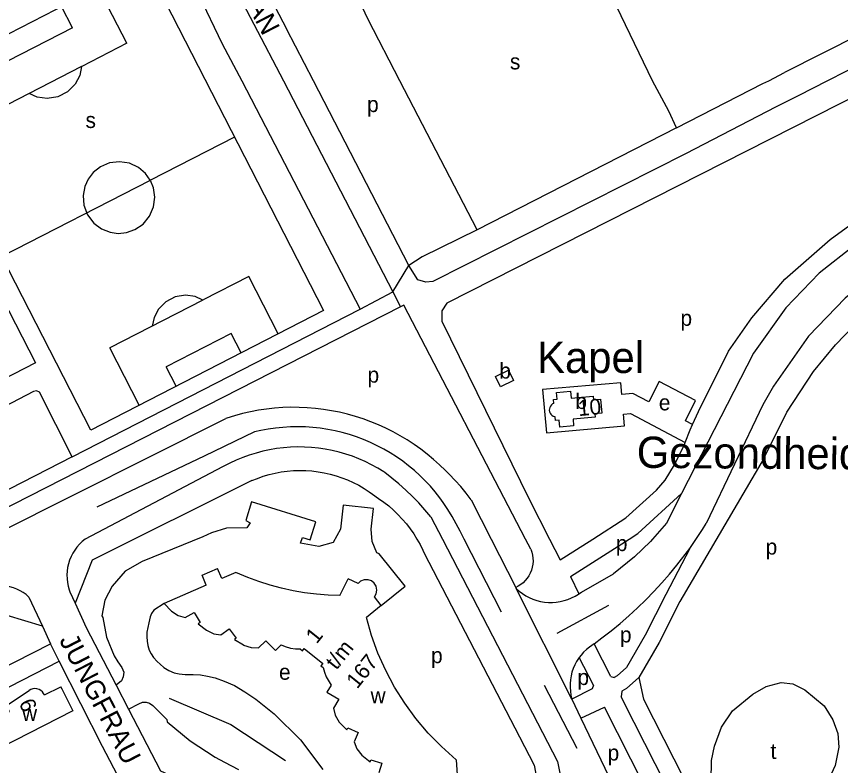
# Model space of a CAD drawing. Extents: x 158848 to 160613, y 385889 to 387762.
# Drawn here: x 159449.2 to 159660, y 386924.8 to 387116.4 of the extents above; entities that cross this region are included whole.
import ezdxf

# ---------------------------------------------------------------- set-up
doc = ezdxf.new("R2010")
doc.units = 0
for name, color, linetype in [('BLT_Basislijn', 7, 'Continuous'), ('BLT_Bebouwing', 7, 'Continuous'), ('BLT_Bebouwing_beschrifting', 7, 'Continuous'), ('BLT_Centroide', 7, 'Continuous'), ('BLT_Huisnummer', 7, 'Continuous'), ('BLT_Huisnummer_reeks', 7, 'Continuous'), ('BLT_Straatnaam', 7, 'Continuous'), ('BLT_Vlakafsluiter', 7, 'Continuous')]:
    doc.layers.add(name, color=color, linetype=linetype)

msp = doc.modelspace()

# ---------------------------------------------------------------- linework, layer by layer
at = {"layer": 'BLT_Basislijn'}
for p, q in [((159712.26, 387135.93), (159645.73, 387102.09)), ((159422.56, 387099.42), (159482.14, 387130.03)), ((159477.37, 387109.59), (159470.08, 387123.78)), ((159463.48, 387113.51), (159460.68, 387118.95)), ((159463.48, 387113.51), (159447.03, 387105.06)), ((159477.37, 387109.59), (159465.86, 387103.67)), ((159465.8, 387103.64), (159441.7, 387091.26)), ((159618.04, 387087.93), (159640.13, 387099.3)), ((159649.19, 387096.1), (159643.38, 387093.22)), ((159618.04, 387087.93), (159567.07, 387061.89)), ((159504.93, 387085.56), (159483.5, 387074.55)), ((159483.37, 387074.49), (159445.44, 387055)), ((159508.61, 387049.92), (159496.93, 387043.92)), ((159516.12, 387035.28), (159508.61, 387049.92)), ((159537.13, 387041.58), (159545.51, 387045.96)), ((159496.85, 387043.88), (159473.08, 387031.67)), ((159547.47, 387042.18), (159539.05, 387037.88)), ((159548.32, 387042.61), (159547.47, 387042.18)), ((159579.44, 386982.75), (159548.32, 387042.61)), ((159463.38, 387003.77), (159537.13, 387041.58)), ((159539.05, 387037.88), (159380.58, 386957.05)), ((159504.12, 387035.32), (159487.49, 387026.78)), ((159506.64, 387030.41), (159504.12, 387035.32)), ((159480.6, 387017.03), (159473.08, 387031.67)), ((159490.01, 387021.87), (159487.49, 387026.78)), ((159622.17, 387012.06), (159623.71, 387015.42)), ((159414.98, 386969.58), (159502.74, 387013.62)), ((159620.29, 387007.45), (159621.54, 387010.68)), ((159621.54, 387010.68), (159622.17, 387012.06)), ((159463.38, 387003.77), (159378.76, 386960.61)), ((159501.9, 387001.21), (159466.71, 386982.75)), ((159509.37, 386997.7), (159468.51, 386977.36)), ((159540.27, 386994.28), (159541.83, 386993.16)), ((159565.56, 386992.79), (159570.64, 386982.75)), ((159555.21, 386988.48), (159558.18, 386982.75)), ((159563.71, 386982.75), (159562.69, 386984.74)), ((159558.18, 386982.75), (159587.6, 386925.88)), ((159573.32, 386964.04), (159563.71, 386982.75)), ((159570.64, 386982.75), (159576.91, 386970.36)), ((159580.8, 386980.14), (159579.44, 386982.75)), ((159585.56, 386982.75), (159588.27, 386977.43)), ((159588.27, 386977.43), (159596.62, 386982.75)), ((159590.95, 386973.21), (159605.93, 386982.75)), ((159553.49, 386979.15), (159577.91, 386932.14)), ((159468.51, 386977.36), (159464.16, 386966.38)), ((159590.95, 386973.21), (159593.11, 386968.77)), ((159593.73, 386969.21), (159601.93, 386973.9)), ((159576.91, 386970.36), (159577.06, 386970.08)), ((159462.82, 386969.28), (159464.16, 386966.38)), ((159593.11, 386968.77), (159593.73, 386969.21)), ((159452.37, 386967.93), (159455.8, 386960.45)), ((159464.16, 386966.38), (159467.02, 386960.16)), ((159600.63, 386965.76), (159587.41, 386958.57)), ((159455.8, 386960.45), (159457.86, 386955.95)), ((159377.94, 386915.35), (159457.86, 386955.95)), ((159460.12, 386951.5), (159457.86, 386955.95)), ((159601.25, 386947.64), (159597.01, 386956)), ((159380.24, 386910.9), (159460.12, 386951.5)), ((159596.8, 386945.36), (159593.17, 386952.51)), ((159601.25, 386947.64), (159602.07, 386947.32)), ((159584.24, 386945.35), (159592.58, 386929.24)), ((159596.8, 386945.36), (159596.47, 386944.43)), ((159637.56, 386943.05), (159640.99, 386945.06)), ((159640.99, 386945.06), (159644.86, 386946.05)), ((159644.86, 386946.05), (159647.8, 386945.7)), ((159647.8, 386945.7), (159650.87, 386944.19)), ((159596.47, 386944.43), (159591.31, 386941.79)), ((159604.1, 386943.87), (159603.91, 386942.41)), ((159632.42, 386938.82), (159637.56, 386943.05)), ((159650.87, 386944.19), (159655.81, 386940.09)), ((159591.31, 386941.79), (159593.58, 386936.96)), ((159607.24, 386935.86), (159603.91, 386942.41)), ((159593.58, 386936.96), (159599.65, 386939.76)), ((159642.66, 386855.15), (159599.65, 386939.76)), ((159629.56, 386934.65), (159632.42, 386938.82)), ((159655.81, 386940.09), (159658.09, 386936.54)), ((159593.58, 386936.96), (159622.47, 386876.62)), ((159658.09, 386936.54), (159659.35, 386933)), ((159648.81, 386854.1), (159607.24, 386935.86)), ((159627.81, 386929.77), (159629.56, 386934.65)), ((159659.35, 386933), (159659.59, 386929.52)), ((159577.91, 386932.14), (159581.66, 386924.93)), ((159627, 386926.08), (159627.81, 386929.77)), ((159659.59, 386929.52), (159658.64, 386924.87)), ((159626.97, 386920.9), (159627, 386926.08)), ((159658.64, 386924.87), (159657.14, 386921.53))]:
    msp.add_line(p, q, dxfattribs=at)
for points in [[(159462.95, 387205.39), (159500.19, 387133.64), (159502.33, 387129.02), (159517.49, 387100), (159545.51, 387045.96)], [(159823.15, 387177.85), (159809.32, 387170.86), (159746.21, 387138.49), (159701.32, 387115.11), (159671.47, 387100), (159559.25, 387043.07), (159557.97, 387041.11), (159558.04, 387038.5), (159580.37, 386992.95), (159585.56, 386982.75)], [(159623.71, 387015.42), (159631.38, 387030.86), (159637.32, 387039.39), (159645.79, 387049.2), (159657.37, 387059.37), (159670.23, 387068.78), (159719.14, 387100), (159823.15, 387164.91)], [(159823.15, 387159.28), (159773.42, 387128.16), (159760.94, 387120.62), (159728.37, 387100), (159675.31, 387066.01), (159663.73, 387057.91), (159654.6, 387050.75), (159646.07, 387041.94), (159637.74, 387030.32), (159619.36, 386994.41)], [(159823.15, 387147.72), (159746.52, 387100), (159703.19, 387072.74), (159675.19, 387055.74), (159661.19, 387044.39), (159651.8, 387034.62), (159642.89, 387021.89), (159640.19, 387017.12), (159625.68, 386986.72)], [(159618.04, 387087.93), (159616.11, 387092.17), (159611.92, 387100), (159590.13, 387145.14)], [(159489.23, 387134.67), (159495.78, 387122.17), (159501.77, 387109.41), (159506.85, 387100), (159537.13, 387041.58)], [(159536.3, 387132.98), (159518.07, 387123.7), (159515.4, 387121.07), (159515.36, 387118.83), (159518.24, 387113.29)], [(159482.14, 387130.03), (159527.77, 387041.21), (159468.2, 387010.6), (159422.56, 387099.42)], [(159715.29, 387129.57), (159698.9, 387121.52), (159656.71, 387100), (159649.19, 387096.1)], [(159567.07, 387061.89), (159547.26, 387100), (159539.13, 387115.69), (159536.12, 387122.2)], [(159549.57, 387052.74), (159525.15, 387100), (159518.24, 387113.29)], [(159465.79, 387103.6), (159465.35, 387101.36), (159464.18, 387099.08), (159462.25, 387097.13), (159459.74, 387095.84), (159457.02, 387095.43), (159454.49, 387095.81), (159452.41, 387096.76)], [(159640.13, 387099.3), (159641.67, 387100), (159645.73, 387102.09)], [(159643.38, 387093.22), (159620.57, 387081.4), (159555.73, 387048.64), (159553.9, 387048.45), (159551.9, 387049.06), (159549.57, 387052.74)], [(159419.08, 387085.16), (159423.4, 387087.37), (159454.01, 387027.8), (159365.2, 386982.16)], [(159483.4, 387074.6), (159482.17, 387076.3), (159480.39, 387077.81), (159478.12, 387078.88), (159475.53, 387079.29), (159472.94, 387078.96), (159470.63, 387077.96), (159468.81, 387076.51), (159467.53, 387074.84), (159466.66, 387072.93), (159466.24, 387070.64), (159466.44, 387068.13), (159467.36, 387065.69), (159468.94, 387063.6), (159470.95, 387062.1), (159473.12, 387061.24), (159475.2, 387060.95), (159477.29, 387061.15), (159479.49, 387061.92), (159481.56, 387063.34), (159483.23, 387065.35), (159484.25, 387067.76), (159484.56, 387070.25), (159484.23, 387072.56), (159483.45, 387074.51)], [(159567.07, 387061.89), (159552.95, 387054.96), (159549.57, 387052.74)], [(159496.89, 387043.9), (159494.86, 387044.78), (159492.42, 387045.12), (159489.81, 387044.69), (159487.4, 387043.45), (159485.53, 387041.58), (159484.39, 387039.4), (159483.92, 387037.23)], [(159545.51, 387045.96), (159547.47, 387042.18)], [(159653.09, 387025.66), (159658.73, 387032.44), (159663.57, 387037.48), (159666.38, 387039.82)], [(159640.5, 387003.56), (159646.33, 387015.21), (159653.09, 387025.66)], [(159620.35, 387013.01), (159622.91, 387018.22), (159613.63, 387023.08), (159611.01, 387017.87)], [(159611.01, 387017.87), (159606.93, 387020), (159604.05, 387019.73), (159603.79, 387022.73), (159583.81, 387020.99), (159584.79, 387009.97), (159604.73, 387011.74), (159604.49, 387014.75), (159606.25, 387014.89), (159620.29, 387007.45)], [(159463.38, 387003.77), (159455.05, 387020.3), (159454.32, 387020.68), (159453.55, 387020.51), (159368.35, 386976.03)], [(159558.95, 387000.27), (159557.45, 387001.73), (159555.9, 387003.13), (159554.29, 387004.47), (159552.63, 387005.74), (159550.93, 387006.95), (159549.18, 387008.1), (159547.39, 387009.17), (159545.55, 387010.18), (159543.68, 387011.12), (159541.78, 387011.99), (159539.85, 387012.78), (159537.88, 387013.49), (159535.89, 387014.14), (159533.88, 387014.7), (159531.84, 387015.19), (159529.79, 387015.6), (159527.73, 387015.93), (159525.65, 387016.18), (159523.57, 387016.35), (159521.48, 387016.44), (159519.39, 387016.46), (159517.3, 387016.39), (159515.21, 387016.24), (159513.14, 387016.01), (159511.07, 387015.71), (159509.01, 387015.32), (159506.97, 387014.86), (159504.95, 387014.31), (159502.96, 387013.7), (159502.74, 387013.62)], [(159622.17, 387012.06), (159620.35, 387013.01)], [(159557.5, 386993.3), (159556.32, 386994.81), (159555.07, 386996.26), (159553.77, 386997.65), (159552.4, 386999), (159550.99, 387000.28), (159549.52, 387001.5), (159548, 387002.66), (159546.43, 387003.76), (159544.82, 387004.79), (159543.16, 387005.75), (159541.47, 387006.64), (159539.74, 387007.46), (159537.98, 387008.21), (159536.19, 387008.88), (159534.38, 387009.48), (159532.54, 387010), (159530.68, 387010.44), (159528.8, 387010.81), (159526.91, 387011.09), (159525.01, 387011.3), (159523.1, 387011.43), (159521.19, 387011.47), (159519.27, 387011.44), (159517.36, 387011.33), (159515.46, 387011.14), (159513.57, 387010.86), (159511.69, 387010.51), (159510.1, 387010.15)], [(159510.1, 387010.15), (159497.21, 387003.99), (159469.72, 386990.88)], [(159543.14, 386999.98), (159541.61, 387000.92), (159540.04, 387001.78), (159538.43, 387002.57), (159536.79, 387003.29), (159535.12, 387003.94), (159533.42, 387004.51), (159531.7, 387005), (159529.96, 387005.42), (159528.2, 387005.76), (159526.43, 387006.02), (159524.64, 387006.2), (159522.85, 387006.3), (159521.06, 387006.32), (159519.27, 387006.26), (159517.49, 387006.12), (159515.71, 387005.9), (159513.94, 387005.6), (159512.19, 387005.23), (159510.46, 387004.77), (159508.74, 387004.24), (159507.06, 387003.63), (159505.4, 387002.95), (159503.78, 387002.2), (159502.19, 387001.37), (159501.9, 387001.21)], [(159596.62, 386982.75), (159605.13, 386988.17), (159612.92, 386995.29), (159615.15, 386997.84), (159617.52, 387001.72), (159620.03, 387006.77), (159620.29, 387007.45)], [(159640.5, 387003.56), (159618.91, 386966.77), (159613.6, 386956.3), (159608.45, 386947.37)], [(159509.37, 386997.7), (159510.83, 386998.29), (159512.31, 386998.81), (159513.83, 386999.26), (159515.36, 386999.63), (159516.91, 386999.92), (159518.47, 387000.13), (159520.04, 387000.26), (159521.62, 387000.32), (159523.19, 387000.29), (159524.77, 387000.18), (159526.33, 386999.99), (159527.89, 386999.73), (159529.43, 386999.38), (159530.94, 386998.96), (159532.44, 386998.46), (159533.91, 386997.88), (159535.35, 386997.24), (159536.75, 386996.52), (159538.11, 386995.73), (159539.43, 386994.87), (159540.27, 386994.28)], [(159555.21, 386988.48), (159553.7, 386990.27), (159552.12, 386992), (159550.48, 386993.67), (159548.79, 386995.29), (159547.05, 386996.85), (159545.25, 386998.35), (159543.4, 386999.79), (159543.14, 386999.98)], [(159565.56, 386992.79), (159564.24, 386994.51), (159562.86, 386996.17), (159561.41, 386997.78), (159559.91, 386999.33), (159558.95, 387000.27)], [(159605.93, 386982.75), (159608.18, 386984.18), (159619.36, 386994.41)], [(159619.36, 386994.41), (159615.47, 386986.8), (159611.93, 386982.75)], [(159542.53, 386965.76), (159548.66, 386970.75), (159541.96, 386979.01), (159541.38, 386979.24), (159540.22, 386982.15), (159539.94, 386985.27), (159540.53, 386990.54), (159532.8, 386991.41), (159532.11, 386985.27), (159530.23, 386981.92), (159526.54, 386980.88), (159521.85, 386981.74), (159522.38, 386983.15), (159524.31, 386982.59), (159525.81, 386987.17), (159509.34, 386992.3), (159507.84, 386987.53), (159508.98, 386986.9), (159508.11, 386985.66), (159502.94, 386985.52), (159499.05, 386984.32), (159496.89, 386983.35), (159481.35, 386977.06), (159477, 386974.52), (159473.67, 386970.74), (159471.81, 386967.14), (159470.99, 386963.16), (159471.28, 386962.67), (159472.2, 386957.63), (159474.15, 386952.89), (159475.09, 386951.36), (159476.09, 386949.87), (159476.64, 386948.74), (159476.47, 386947.48), (159476.07, 386946.51), (159474.68, 386945.37)], [(159541.83, 386993.16), (159543.15, 386992.23), (159544.41, 386991.23), (159545.63, 386990.18), (159546.79, 386989.06), (159547.89, 386987.89), (159548.94, 386986.66), (159549.92, 386985.38), (159550.84, 386984.06), (159551.65, 386982.75)], [(159562.69, 386984.74), (159561.71, 386986.64), (159560.66, 386988.5), (159559.55, 386990.32), (159558.36, 386992.1), (159557.5, 386993.3)], [(159621.45, 386980.35), (159624.73, 386985.23), (159625.68, 386986.72)], [(159466.71, 386982.75), (159465.96, 386982.13), (159465.27, 386981.46), (159464.64, 386980.72), (159464.06, 386979.94), (159463.56, 386979.12), (159463.12, 386978.26), (159462.76, 386977.36), (159462.47, 386976.43), (159462.26, 386975.49), (159462.12, 386974.53), (159462.07, 386973.57), (159462.1, 386972.6), (159462.21, 386971.64), (159462.39, 386970.69), (159462.66, 386969.76), (159462.82, 386969.28)], [(159551.65, 386982.75), (159552.44, 386981.35), (159553.15, 386979.9), (159553.49, 386979.15)], [(159611.93, 386982.75), (159611.43, 386982.18), (159607.35, 386978.21), (159601.93, 386973.9)], [(159580.8, 386980.14), (159581.05, 386979.41), (159581.23, 386978.65), (159581.33, 386977.88), (159581.36, 386977.1), (159581.3, 386976.32), (159581.16, 386975.55), (159580.94, 386974.8), (159580.65, 386974.08), (159580.29, 386973.39), (159579.86, 386972.74), (159579.36, 386972.14), (159578.81, 386971.59), (159578.2, 386971.11), (159577.54, 386970.68), (159576.91, 386970.36)], [(159597.01, 386956), (159598.99, 386957.47), (159601.34, 386959.3), (159603.63, 386961.2), (159605.87, 386963.16), (159608.05, 386965.18), (159610.18, 386967.25), (159612.26, 386969.38), (159614.27, 386971.57), (159616.23, 386973.81), (159618.13, 386976.1), (159621.45, 386980.35)], [(159621.45, 386980.35), (159615.35, 386968.59), (159610.08, 386958.21), (159605.31, 386949.93), (159602.89, 386947.8), (159602.07, 386947.32)], [(159452.37, 386967.93), (159451.65, 386968.54), (159450.89, 386969.08), (159450.09, 386969.55), (159449.25, 386969.95), (159448.37, 386970.28), (159447.48, 386970.54), (159446.56, 386970.71), (159445.63, 386970.81), (159445.16, 386970.82)], [(159577.06, 386970.08), (159577.82, 386969.41), (159578.63, 386968.8), (159579.49, 386968.26), (159580.39, 386967.79), (159581.32, 386967.4), (159582.28, 386967.07), (159583.27, 386966.83), (159584.27, 386966.66), (159585.28, 386966.57), (159586.29, 386966.56), (159587.3, 386966.63), (159588.3, 386966.78), (159589.29, 386967.01), (159590.26, 386967.32), (159591.2, 386967.7), (159592.1, 386968.15), (159592.97, 386968.67), (159593.11, 386968.77)], [(159486.92, 386966.3), (159484.35, 386964.6), (159483.75, 386963.75), (159483.41, 386962.83), (159483.04, 386961.37), (159482.56, 386958.94), (159482.51, 386957.74), (159482.57, 386956.68), (159482.77, 386955.56), (159483.15, 386954.38), (159483.66, 386953.37), (159484.26, 386952.45), (159485.13, 386951.48), (159485.97, 386950.75), (159486.91, 386949.92), (159488.15, 386949.1), (159489.48, 386948.57), (159490.76, 386948.25), (159492.37, 386948.13), (159494.35, 386948.12), (159496.23, 386948.01), (159498.08, 386947.68), (159500, 386947.23), (159502.28, 386946.45), (159504.93, 386945.29), (159507.64, 386943.72), (159510.42, 386941.77), (159515.09, 386938.08), (159521.87, 386931.43), (159527.59, 386923.85)], [(159455.8, 386960.45), (159446.79, 386963.22), (159440.57, 386963.22), (159434.83, 386960.83), (159394.63, 386939.76), (159382.67, 386934.97), (159375.49, 386932.58), (159369.75, 386931.62), (159369.54, 386931.59)], [(159467.02, 386960.16), (159474.68, 386945.37)], [(159597.01, 386956), (159595.78, 386955.14), (159595.01, 386954.51), (159594.29, 386953.83), (159593.63, 386953.09), (159593.17, 386952.51)], [(159378.73, 386868.21), (159381.51, 386870.25), (159384.89, 386871.94), (159390.8, 386873.2), (159397.02, 386873.2), (159403.72, 386871.28), (159415.21, 386866.02), (159440.57, 386853.09), (159443.92, 386851.65), (159447.27, 386852.13), (159475.51, 386913.9), (159475.98, 386920.61), (159471.2, 386929.7), (159460.12, 386951.5)], [(159593.17, 386952.51), (159592.5, 386951.46), (159592.03, 386950.58), (159591.64, 386949.67), (159591.32, 386948.73), (159591.08, 386947.77), (159590.92, 386946.79), (159590.83, 386945.8), (159590.83, 386944.81), (159590.9, 386943.82), (159591.06, 386942.84), (159591.31, 386941.79)], [(159608.45, 386947.37), (159605.24, 386944.54), (159604.1, 386943.87)], [(159608.45, 386947.37), (159609.58, 386941.77), (159635.45, 386891)], [(159474.68, 386945.37), (159477.85, 386939.23)], [(159477.85, 386939.23), (159480.51, 386940.65), (159481.41, 386941.02), (159482.39, 386941.03), (159483.19, 386940.79), (159484.1, 386940.17), (159487.6, 386936.62), (159487.75, 386936.01), (159493.62, 386931.13), (159500, 386926.95), (159502.36, 386925.67), (159506.01, 386923.84)], [(159488.27, 386942.07), (159503.99, 386935.29), (159517.97, 386926.12)], [(159477.85, 386939.23), (159486.03, 386923.44), (159520.96, 386907.65), (159525.75, 386903.34), (159529.1, 386898.55), (159538.94, 386879.26)], [(159587.6, 386925.88), (159589.99, 386914), (159595.45, 386903.65), (159602.75, 386896.61)], [(159581.66, 386924.93), (159583.96, 386912.85), (159587.17, 386906.95)]]:
    msp.add_lwpolyline(points, dxfattribs=at)
at = {"layer": 'BLT_Bebouwing'}
for p, q in [((159531.89, 386968.29), (159534.01, 386972.6)), ((159536.58, 386971.37), (159534.01, 386972.6)), ((159497.71, 386970.97), (159486.92, 386966.3)), ((159542.53, 386965.76), (159538.72, 386962.71))]:
    msp.add_line(p, q, dxfattribs=at)
for points in [[(159571.77, 387024.35), (159575.06, 387025.95), (159576.36, 387023.3), (159573.06, 387021.69), (159571.77, 387024.35)], [(159586.68, 387017.47), (159586.59, 387018.44), (159587.51, 387018.52), (159587.34, 387020.29), (159590.9, 387020.62), (159591.07, 387018.81), (159596.76, 387019.35), (159596.85, 387018.38), (159598.59, 387018.54), (159598.92, 387014.99), (159597.15, 387014.83), (159597.24, 387013.97), (159591.59, 387013.43), (159591.74, 387011.75), (159588.19, 387011.41), (159588.02, 387013.18), (159587.1, 387013.1), (159587.01, 387014.06)], [(159586.68, 387017.47), (159586.34, 387017.31), (159586.05, 387017.07), (159585.81, 387016.78), (159585.64, 387016.45), (159585.54, 387016.08), (159585.52, 387015.71), (159585.59, 387015.34), (159585.72, 387014.99), (159585.93, 387014.67), (159586.2, 387014.41), (159586.52, 387014.21), (159586.88, 387014.09), (159587.01, 387014.06)], [(159497.71, 386970.97), (159496.65, 386973.5), (159500.6, 386975.21)], [(159531.89, 386968.29), (159528.9, 386968.41), (159525.9, 386968.65), (159522.91, 386969.03), (159519.94, 386969.55), (159516.99, 386970.19), (159514.07, 386970.97), (159511.2, 386971.87), (159508.37, 386972.9), (159505.28, 386974.22), (159501.69, 386972.69), (159500.6, 386975.21)], [(159542.53, 386965.76), (159540.74, 386968), (159541.19, 386968.78), (159541.37, 386969.73), (159541.18, 386970.7), (159540.69, 386971.51), (159540.01, 386972.06), (159539.12, 386972.37), (159538.14, 386972.35), (159537.24, 386971.97), (159536.58, 386971.37)], [(159486.92, 386966.3), (159488.83, 386964.31), (159490.58, 386963.23), (159492.36, 386962.68), (159494.63, 386964.01)], [(159494.63, 386964.01), (159496.16, 386961.41), (159495.63, 386961.12)], [(159561.71, 386926.31), (159557.9, 386929.72), (159554.53, 386933.15), (159551.4, 386936.85), (159548.52, 386940.77), (159545.93, 386944.89), (159543.64, 386949.18), (159541.67, 386953.6), (159540.03, 386958.12), (159538.72, 386962.71)], [(159495.63, 386961.12), (159497.76, 386959.42), (159499.63, 386958.55), (159501.5, 386958.26), (159503.59, 386959.84), (159505.39, 386957.44), (159504.92, 386957.08)], [(159504.92, 386957.08), (159507.22, 386955.67), (159507.25, 386955.63), (159509.2, 386955.01), (159511.07, 386954.92), (159512.96, 386956.76), (159515.44, 386954.23)], [(159515.44, 386954.23), (159516.94, 386955.68), (159517.9, 386955.25), (159519.29, 386954.87), (159520.6, 386954.67), (159521.76, 386954.66), (159522.38, 386954.21)], [(159522.38, 386954.21), (159522.81, 386954.73), (159527.53, 386950.92)], [(159527.53, 386950.92), (159527.04, 386950.33), (159527.67, 386949.92), (159528, 386948.75), (159528.45, 386947.56), (159529.19, 386946.21), (159529.73, 386945.43), (159528.62, 386943.64)], [(159456.32, 386942.88), (159460.49, 386945)], [(159460.49, 386945), (159463.61, 386938.84)], [(159460.79, 386944.42), (159460.49, 386945)], [(159440.35, 386929.47), (159438.08, 386933.92), (159447.38, 386938.67), (159446.63, 386940.19), (159452.45, 386944.04)], [(159456.32, 386942.88), (159456.11, 386943.29), (159455.81, 386943.69), (159455.41, 386944.04), (159454.93, 386944.31), (159454.4, 386944.47), (159453.86, 386944.52), (159453.33, 386944.44), (159452.86, 386944.28), (159452.45, 386944.04)], [(159528.62, 386943.64), (159531.64, 386941.77), (159530.26, 386939.52), (159530.74, 386937.73), (159531.77, 386935.95), (159533.68, 386933.99)], [(159463.61, 386938.84), (159441.35, 386927.52), (159440.35, 386929.47)], [(159533.68, 386933.99), (159533.92, 386934.52), (159536.64, 386933.25), (159535.55, 386930.86), (159536.26, 386929.14), (159537.52, 386927.51), (159539.66, 386925.74)], [(159539.66, 386925.74), (159539.86, 386926.3), (159542.65, 386925.42), (159541.85, 386922.93), (159542.76, 386921.31), (159544.21, 386919.83), (159546.62, 386918.3)], [(159561.71, 386926.31), (159561.93, 386922.45), (159564.68, 386922.59)]]:
    msp.add_lwpolyline(points, dxfattribs=at)
at = {"layer": 'BLT_Vlakafsluiter'}
for p, q in [((159545.51, 387045.96), (159549.57, 387052.74)), ((159591.31, 386941.79), (159577.06, 386970.08))]:
    msp.add_line(p, q, dxfattribs=at)

# ---------------------------------------------------------------- texts
at = {"layer": 'BLT_Bebouwing_beschrifting'}
msp.add_text('Kapel', height=8, dxfattribs=at).set_placement((159582.4, 387025.23))
msp.add_text('Gezondheidscentrum', height=7.9999, rotation=359.5665, dxfattribs=at).set_placement((159607.87, 387000.99))
at = {"layer": 'BLT_Centroide'}
for s, p in [('s', (159575.43, 387102.89)), ('p', (159538.88, 387091.98)), ('s', (159466.83, 387087.91)), ('p', (159619.08, 387037.3)), ('b', (159572.72, 387023.81)), ('p', (159539, 387022.77)), ('b', (159592.18, 387016.03)), ('e', (159613.54, 387015.68)), ('p', (159602.54, 386979.68)), ('p', (159640.87, 386978.79)), ('p', (159603.59, 386956.32)), ('p', (159555.25, 386951.02)), ('e', (159516.34, 386946.77)), ('p', (159592.7, 386945.43)), ('w', (159539.77, 386940.78)), ('w', (159450.6, 386936.25)), ('t', (159642.12, 386926.51)), ('p', (159600.43, 386926.11))]:
    msp.add_text(s, height=4, dxfattribs=at).set_placement(p)
at = {"layer": 'BLT_Huisnummer'}
for s, rotation, p in [('10', 5.3882, (159593.02, 387014.2)), ('6', 293.8476, (159449.71, 386940.86))]:
    msp.add_text(s, height=4, rotation=rotation, dxfattribs=at).set_placement(p)
at = {"layer": 'BLT_Huisnummer_reeks'}
for s, p in [('1', (159525.97, 386955.76)), ('t/m', (159531.02, 386949.09)), ('167', (159536.34, 386944.25))]:
    msp.add_text(s, height=4, rotation=51.2772, dxfattribs=at).set_placement(p)
at = {"layer": 'BLT_Straatnaam'}
for s, rotation, p in [('OUDE BOSSCHE BAAN', 297.213, (159478.49, 387176.98)), ('JUNGFRAU', 297.4499, (159459.99, 386956.92))]:
    msp.add_text(s, height=5, rotation=rotation, dxfattribs=at).set_placement(p)

doc.saveas('drawing.dxf')
